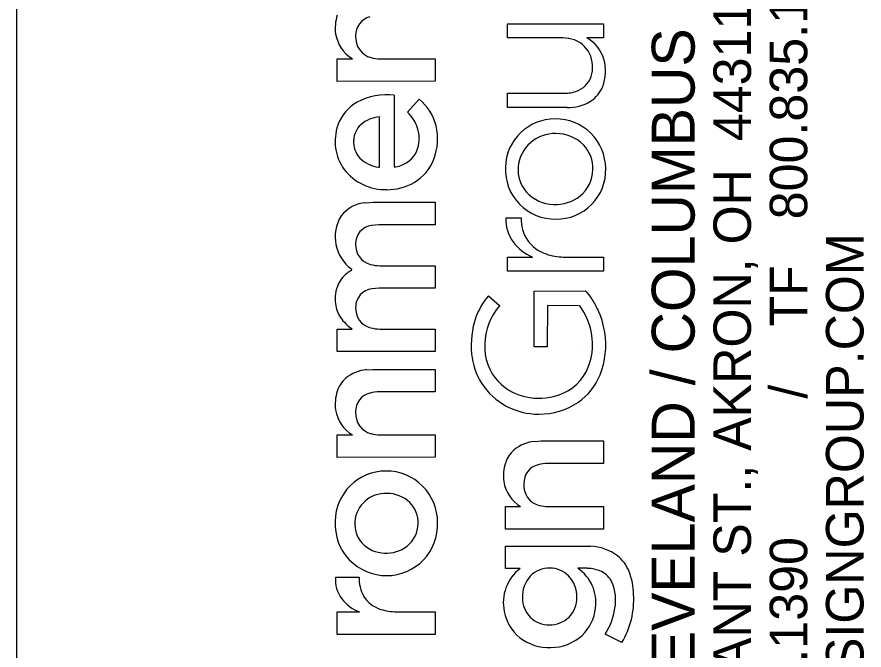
# Model space of a CAD drawing. Extents: x -0.6 to 34, y 0 to 22.
# Drawn here: x 32 to 33.125, y 3.095 to 3.936 of the extents above; entities that cross this region are included whole.
import ezdxf

# ---------------------------------------------------------------- set-up
doc = ezdxf.new("R2010")
doc.units = 0
doc.layers.add('SH_Cut_Line', color=7, linetype='Continuous')
doc.layers.add('SH_Data', color=7, linetype='Continuous')

msp = doc.modelspace()

# ---------------------------------------------------------------- linework, layer by layer
at = {"layer": 'SH_Cut_Line'}
for p, q in [((32.6515, 3.908), (32.6515, 3.9267)), ((32.6515, 3.9267), (32.7791, 3.9266)), ((32.7791, 3.9266), (32.7791, 3.908)), ((32.7249, 3.908), (32.6515, 3.908)), ((32.7328, 3.9073), (32.7249, 3.908)), ((32.7791, 3.908), (32.7569, 3.908)), ((32.4254, 3.8503), (32.4254, 3.8802)), ((32.4254, 3.8802), (32.4455, 3.8802)), ((32.4822, 3.8802), (32.5557, 3.8802)), ((32.5557, 3.8802), (32.5557, 3.8504)), ((32.5557, 3.8504), (32.4254, 3.8503)), ((32.5011, 3.8321), (32.5012, 3.7366)), ((32.5188, 3.8093), (32.5342, 3.8266)), ((32.6515, 3.8344), (32.7291, 3.8345)), ((32.6517, 3.8154), (32.6515, 3.8344)), ((32.7307, 3.8154), (32.6517, 3.8154)), ((32.4814, 3.7364), (32.4814, 3.803)), ((32.4802, 3.7363), (32.4814, 3.7364)), ((32.4633, 3.6891), (32.4726, 3.6897)), ((32.4726, 3.6897), (32.5556, 3.6897)), ((32.5556, 3.6897), (32.5557, 3.6598)), ((32.6493, 3.6691), (32.6698, 3.6691)), ((32.4806, 3.6598), (32.471, 3.6588)), ((32.5557, 3.6598), (32.4806, 3.6598)), ((32.6515, 3.598), (32.6515, 3.617)), ((32.6515, 3.617), (32.6848, 3.617)), ((32.726, 3.617), (32.7791, 3.617)), ((32.7791, 3.617), (32.779, 3.598)), ((32.4444, 3.5992), (32.4446, 3.6007)), ((32.4822, 3.6055), (32.5557, 3.6055)), ((32.5557, 3.6055), (32.5557, 3.5757)), ((32.779, 3.598), (32.6515, 3.598)), ((32.4809, 3.5757), (32.4714, 3.5747)), ((32.5557, 3.5757), (32.4809, 3.5757)), ((32.6868, 3.5718), (32.7552, 3.5719)), ((32.6868, 3.4978), (32.6868, 3.5718)), ((32.6264, 3.5655), (32.6411, 3.5524)), ((32.7045, 3.5524), (32.7043, 3.4978)), ((32.7474, 3.5523), (32.7045, 3.5524)), ((32.4254, 3.4915), (32.4254, 3.5214)), ((32.4254, 3.5214), (32.4451, 3.5214)), ((32.4821, 3.5214), (32.5557, 3.5214)), ((32.5557, 3.5214), (32.5557, 3.4916)), ((32.75, 3.5), (32.75, 3.5)), ((32.5557, 3.4916), (32.4254, 3.4915)), ((32.7043, 3.4978), (32.6868, 3.4978)), ((32.4644, 3.4674), (32.4729, 3.4678)), ((32.4729, 3.4678), (32.5557, 3.4678)), ((32.5557, 3.4678), (32.5557, 3.438)), ((32.5557, 3.438), (32.4814, 3.438)), ((32.4254, 3.3509), (32.4254, 3.3807)), ((32.4254, 3.3807), (32.4455, 3.3807)), ((32.4822, 3.3807), (32.5557, 3.3807)), ((32.5557, 3.3807), (32.5557, 3.351)), ((32.6878, 3.3722), (32.6963, 3.3727)), ((32.6963, 3.3727), (32.7792, 3.3727)), ((32.7792, 3.3727), (32.7792, 3.3429)), ((32.5557, 3.351), (32.4254, 3.3509)), ((32.7792, 3.3429), (32.7048, 3.3428)), ((32.6489, 3.2557), (32.6489, 3.2855)), ((32.6489, 3.2855), (32.669, 3.2855)), ((32.7057, 3.2855), (32.7791, 3.2855)), ((32.7791, 3.2855), (32.7792, 3.2558)), ((32.7792, 3.2558), (32.6489, 3.2557)), ((32.6489, 3.2034), (32.6489, 3.2332)), ((32.6489, 3.2332), (32.7524, 3.2332)), ((32.7524, 3.2332), (32.7619, 3.2329)), ((32.6684, 3.2034), (32.6489, 3.2034)), ((32.7576, 3.2036), (32.7449, 3.2036)), ((32.423, 3.1919), (32.4545, 3.1919)), ((32.4254, 3.1159), (32.4254, 3.1458)), ((32.4254, 3.1458), (32.4547, 3.1458)), ((32.5041, 3.1458), (32.5557, 3.1457)), ((32.5557, 3.1457), (32.5556, 3.1159)), ((32.5556, 3.1159), (32.4254, 3.1159)), ((32.8036, 3.1049), (32.7812, 3.116))]:
    msp.add_line(p, q, dxfattribs=at)
for points in [[(32.7328, 3.9073), (32.7249, 3.908), (32.6515, 3.908), (32.6515, 3.9267), (32.7791, 3.9266), (32.7791, 3.908), (32.7569, 3.908)], [(32.4254, 3.8503), (32.4254, 3.8802), (32.4455, 3.8802)], [(32.4822, 3.8802), (32.5557, 3.8802), (32.5557, 3.8504), (32.4254, 3.8503)], [(32.5011, 3.8321), (32.5012, 3.7366)], [(32.5188, 3.8093), (32.5342, 3.8266)], [(32.7307, 3.8154), (32.6517, 3.8154), (32.6515, 3.8344), (32.7291, 3.8345)], [(32.4802, 3.7363), (32.4814, 3.7364), (32.4814, 3.803)], [(32.4633, 3.6891), (32.4726, 3.6897), (32.5556, 3.6897), (32.5557, 3.6598), (32.4806, 3.6598), (32.471, 3.6588)], [(32.6493, 3.6691), (32.6698, 3.6691)], [(32.6515, 3.598), (32.6515, 3.617), (32.6848, 3.617)], [(32.726, 3.617), (32.7791, 3.617), (32.779, 3.598), (32.6515, 3.598)], [(32.4444, 3.5992), (32.4446, 3.6007)], [(32.4822, 3.6055), (32.5557, 3.6055), (32.5557, 3.5757), (32.4809, 3.5757), (32.4714, 3.5747)], [(32.7474, 3.5523), (32.7045, 3.5524), (32.7043, 3.4978), (32.6868, 3.4978), (32.6868, 3.5718), (32.7552, 3.5719)], [(32.6264, 3.5655), (32.6411, 3.5524)], [(32.4254, 3.4915), (32.4254, 3.5214), (32.4451, 3.5214)], [(32.4821, 3.5214), (32.5557, 3.5214), (32.5557, 3.4916), (32.4254, 3.4915)], [(32.4644, 3.4674), (32.4729, 3.4678), (32.5557, 3.4678), (32.5557, 3.438), (32.4814, 3.438)], [(32.4254, 3.3509), (32.4254, 3.3807), (32.4455, 3.3807)], [(32.4822, 3.3807), (32.5557, 3.3807), (32.5557, 3.351), (32.4254, 3.3509)], [(32.6878, 3.3722), (32.6963, 3.3727), (32.7792, 3.3727), (32.7792, 3.3429), (32.7048, 3.3428)], [(32.6489, 3.2557), (32.6489, 3.2855), (32.669, 3.2855)], [(32.7057, 3.2855), (32.7791, 3.2855), (32.7792, 3.2558), (32.6489, 3.2557)], [(32.6684, 3.2034), (32.6489, 3.2034), (32.6489, 3.2332), (32.7524, 3.2332), (32.7619, 3.2329)], [(32.7576, 3.2036), (32.7449, 3.2036)], [(32.423, 3.1919), (32.4545, 3.1919)], [(32.4254, 3.1159), (32.4254, 3.1458), (32.4547, 3.1458)], [(32.5041, 3.1458), (32.5557, 3.1457), (32.5556, 3.1159), (32.4254, 3.1159)], [(32.8036, 3.1049), (32.7812, 3.116)]]:
    msp.add_lwpolyline(points, dxfattribs=at)
for centre, radius, start, end in [((32.4787, 3.9211), 0.056, 162.274, 187.7917), ((32.4787, 3.9211), 0.056, 162.274, 187.7917), ((32.4748, 3.9116), 0.025, 103.6868, 182.214), ((32.4748, 3.9116), 0.025, 103.6868, 182.214), ((32.4703, 3.9209), 0.0476, 188.9646, 238.6987), ((32.4703, 3.9209), 0.0476, 188.9646, 238.6987), ((32.4774, 3.9085), 0.0276, 175.5844, 255.1382), ((32.4774, 3.9085), 0.0276, 175.5844, 255.1382), ((32.7271, 3.87), 0.0377, 33.5008, 81.3295), ((32.7271, 3.87), 0.0377, 33.5008, 81.3295), ((32.7324, 3.8648), 0.0496, 17.6221, 60.3897), ((32.7324, 3.8648), 0.0496, 17.6221, 60.3897), ((32.4818, 3.9224), 0.0421, 254.0891, 270.5284), ((32.4818, 3.9224), 0.0421, 254.0891, 270.5284), ((32.7241, 3.8695), 0.0405, 346.5618, 31.7539), ((32.7241, 3.8695), 0.0405, 346.5618, 31.7539), ((32.7234, 3.8641), 0.0584, 339.162, 15.6148), ((32.7234, 3.8641), 0.0584, 339.162, 15.6148), ((32.7337, 3.8662), 0.0304, 294.6321, 348.4863), ((32.7337, 3.8662), 0.0304, 294.6321, 348.4863), ((32.7275, 3.8808), 0.0463, 271.952, 294.0894), ((32.7275, 3.8808), 0.0463, 271.952, 294.0894), ((32.739, 3.859), 0.042, 303.1039, 338.1561), ((32.739, 3.859), 0.042, 303.1039, 338.1561), ((32.4918, 3.7487), 0.0839, 83.6212, 118.2845), ((32.4918, 3.7487), 0.0839, 83.6212, 118.2845), ((32.494, 3.7763), 0.0644, 13.5328, 51.3627), ((32.494, 3.7763), 0.0644, 13.5328, 51.3627), ((32.4789, 3.7737), 0.0558, 118.8294, 160.6224), ((32.4789, 3.7737), 0.0558, 118.8294, 160.6224), ((32.7321, 3.8726), 0.0571, 268.627, 301.4778), ((32.7321, 3.8726), 0.0571, 268.627, 301.4778), ((32.4844, 3.7607), 0.0424, 94.0131, 130.8806), ((32.4844, 3.7607), 0.0424, 94.0131, 130.8806), ((32.4803, 3.7702), 0.0549, 19.0387, 45.4432), ((32.4803, 3.7702), 0.0549, 19.0387, 45.4432), ((32.487, 3.7707), 0.0644, 160.5214, 215.7815), ((32.487, 3.7707), 0.0644, 160.5214, 215.7815), ((32.477, 3.7709), 0.0298, 132.9855, 177.1802), ((32.477, 3.7709), 0.0298, 132.9855, 177.1802), ((32.7143, 3.7348), 0.0655, 89.4821, 178.7775), ((32.7143, 3.7348), 0.0655, 89.4821, 178.7775), ((32.7158, 3.7341), 0.0662, 0.4227, 90.7613), ((32.7158, 3.7341), 0.0662, 0.4227, 90.7613), ((32.4872, 3.7743), 0.047, 344.6072, 17.0067), ((32.4872, 3.7743), 0.047, 344.6072, 17.0067), ((32.4829, 3.7738), 0.0758, 339.3543, 13.3771), ((32.4829, 3.7738), 0.0758, 339.3543, 13.3771), ((32.714, 3.7324), 0.0485, 87.6883, 175.017), ((32.714, 3.7324), 0.0485, 87.6883, 175.017), ((32.7166, 3.7304), 0.0505, 44.912, 90.7591), ((32.7166, 3.7304), 0.0505, 44.912, 90.7591), ((32.4782, 3.7697), 0.0311, 175.0014, 223.2876), ((32.4782, 3.7697), 0.0311, 175.0014, 223.2876), ((32.499, 3.7718), 0.035, 288.0108, 343.5536), ((32.499, 3.7718), 0.035, 288.0108, 343.5536), ((32.7196, 3.7345), 0.0455, 358.3228, 43.8349), ((32.7196, 3.7345), 0.0455, 358.3228, 43.8349), ((32.4855, 3.7783), 0.0423, 225.0645, 262.797), ((32.4855, 3.7783), 0.0423, 225.0645, 262.797), ((32.4955, 3.7698), 0.0626, 300.9439, 338.7322), ((32.4955, 3.7698), 0.0626, 300.9439, 338.7322), ((32.5013, 3.7568), 0.0202, 269.7004, 294.8729), ((32.5013, 3.7568), 0.0202, 269.7004, 294.8729), ((32.7148, 3.7334), 0.0661, 177.5373, 270.9452), ((32.7148, 3.7334), 0.0661, 177.5373, 270.9452), ((32.7108, 3.7331), 0.0453, 175.5147, 221.4205), ((32.7108, 3.7331), 0.0453, 175.5147, 221.4205), ((32.4891, 3.7752), 0.0687, 217.7434, 271.6561), ((32.4891, 3.7752), 0.0687, 217.7434, 271.6561), ((32.7167, 3.7327), 0.0654, 269.3083, 1.6791), ((32.7167, 3.7327), 0.0654, 269.3083, 1.6791), ((32.7193, 3.7337), 0.0457, 308.9038, 359.3095), ((32.7193, 3.7337), 0.0457, 308.9038, 359.3095), ((32.492, 3.777), 0.0706, 269.2053, 300.3357), ((32.492, 3.777), 0.0706, 269.2053, 300.3357), ((32.714, 3.7373), 0.0505, 222.6626, 268.3733), ((32.714, 3.7373), 0.0505, 222.6626, 268.3733), ((32.7157, 3.7386), 0.0518, 266.5531, 308.6725), ((32.7157, 3.7386), 0.0518, 266.5531, 308.6725), ((32.4664, 3.644), 0.0452, 93.9112, 142.3072), ((32.4664, 3.644), 0.0452, 93.9112, 142.3072), ((32.4759, 3.6437), 0.0532, 148.2879, 233.9556), ((32.4759, 3.6437), 0.0532, 148.2879, 233.9556), ((32.6988, 3.6666), 0.0495, 177.1621, 216.2802), ((32.6988, 3.6666), 0.0495, 177.1621, 216.2802), ((32.7173, 3.6664), 0.0476, 176.7699, 252.1504), ((32.7173, 3.6664), 0.0476, 176.7699, 252.1504), ((32.4738, 3.635), 0.024, 96.7576, 181.6251), ((32.4738, 3.635), 0.024, 96.7576, 181.6251), ((32.4758, 3.6324), 0.026, 175.8157, 256.1672), ((32.4758, 3.6324), 0.026, 175.8157, 256.1672), ((32.7098, 3.6755), 0.0637, 216.9153, 246.8862), ((32.7098, 3.6755), 0.0637, 216.9153, 246.8862), ((32.7269, 3.6917), 0.0747, 251.1388, 269.3469), ((32.7269, 3.6917), 0.0747, 251.1388, 269.3469), ((32.4817, 3.6505), 0.045, 254.3463, 270.6103), ((32.4817, 3.6505), 0.045, 254.3463, 270.6103), ((32.4619, 3.5645), 0.0387, 139.5245, 154.847), ((32.4619, 3.5645), 0.0387, 139.5245, 154.847), ((32.4638, 3.5627), 0.0414, 117.9163, 139.243), ((32.4638, 3.5627), 0.0414, 117.9163, 139.243), ((32.4714, 3.5612), 0.0488, 156.0638, 187.3493), ((32.4714, 3.5612), 0.0488, 156.0638, 187.3493), ((32.4742, 3.5506), 0.0243, 96.5532, 179.949), ((32.4742, 3.5506), 0.0243, 96.5532, 179.949), ((32.725, 3.5394), 0.0444, 30.9891, 47.161), ((32.725, 3.5394), 0.0444, 30.9891, 47.161), ((32.7016, 3.5019), 0.0986, 139.7948, 159.137), ((32.7016, 3.5019), 0.0986, 139.7948, 159.137), ((32.6709, 3.5002), 0.1111, 25.3031, 33.9618), ((32.6709, 3.5002), 0.1111, 25.3031, 33.9618), ((32.4646, 3.5597), 0.0418, 186.5579, 213.3885), ((32.4646, 3.5597), 0.0418, 186.5579, 213.3885), ((32.4761, 3.5486), 0.0263, 175.722, 255.7863), ((32.4761, 3.5486), 0.0263, 175.722, 255.7863), ((32.699, 3.5008), 0.0775, 138.258, 179.7006), ((32.699, 3.5008), 0.0775, 138.258, 179.7006), ((32.6789, 3.501), 0.0856, 10.0751, 36.8319), ((32.6789, 3.501), 0.0856, 10.0751, 36.8319), ((32.6704, 3.4999), 0.1117, 8.8034, 25.3348), ((32.6704, 3.4999), 0.1117, 8.8034, 25.3348), ((32.4789, 3.5708), 0.0598, 214.7043, 235.6872), ((32.4789, 3.5708), 0.0598, 214.7043, 235.6872), ((32.7187, 3.4997), 0.1154, 161.1438, 185.6281), ((32.7187, 3.4997), 0.1154, 161.1438, 185.6281), ((32.4819, 3.5652), 0.0438, 253.6672, 270.1498), ((32.4819, 3.5652), 0.0438, 253.6672, 270.1498), ((32.6842, 3.5006), 0.0804, 333.4669, 11.0367), ((32.6842, 3.5006), 0.0804, 333.4669, 11.0367), ((32.6756, 3.4998), 0.1065, 338.2887, 9.2855), ((32.6756, 3.4998), 0.1065, 338.2887, 9.2855), ((32.6881, 3.4973), 0.0668, 176.6658, 223.6912), ((32.6881, 3.4973), 0.0668, 176.6658, 223.6912), ((32.6934, 3.497), 0.0899, 185.5077, 212.0129), ((32.6934, 3.497), 0.0899, 185.5077, 212.0129), ((32.4687, 3.4177), 0.0499, 94.9706, 130.2248), ((32.4687, 3.4177), 0.0499, 94.9706, 130.2248), ((32.4635, 3.426), 0.0402, 132.2238, 161.6823), ((32.4635, 3.426), 0.0402, 132.2238, 161.6823), ((32.6987, 3.4955), 0.0652, 282.8815, 331.8147), ((32.6987, 3.4955), 0.0652, 282.8815, 331.8147), ((32.6984, 3.4917), 0.0824, 305.0306, 337.6757), ((32.6984, 3.4917), 0.0824, 305.0306, 337.6757), ((32.6921, 3.4975), 0.0891, 212.7022, 270.714), ((32.6921, 3.4975), 0.0891, 212.7022, 270.714), ((32.6905, 3.5001), 0.0704, 224.0215, 253.88), ((32.6905, 3.5001), 0.0704, 224.0215, 253.88), ((32.4787, 3.4216), 0.056, 162.274, 187.7917), ((32.4787, 3.4216), 0.056, 162.274, 187.7917), ((32.4748, 3.4121), 0.025, 103.6868, 182.214), ((32.4748, 3.4121), 0.025, 103.6868, 182.214), ((32.4811, 3.392), 0.046, 89.6051, 105.3303), ((32.4811, 3.392), 0.046, 89.6051, 105.3303), ((32.6932, 3.5125), 0.0831, 254.4535, 283.9512), ((32.6932, 3.5125), 0.0831, 254.4535, 283.9512), ((32.6943, 3.4998), 0.0914, 269.3273, 304.1963), ((32.6943, 3.4998), 0.0914, 269.3273, 304.1963), ((32.4703, 3.4214), 0.0476, 188.9646, 238.6987), ((32.4703, 3.4214), 0.0476, 188.9646, 238.6987), ((32.4774, 3.409), 0.0276, 175.5844, 255.1382), ((32.4774, 3.409), 0.0276, 175.5844, 255.1382), ((32.4818, 3.4229), 0.0421, 254.0891, 270.5284), ((32.4818, 3.4229), 0.0421, 254.0891, 270.5284), ((32.6922, 3.3225), 0.0499, 94.9706, 130.2248), ((32.6922, 3.3225), 0.0499, 94.9706, 130.2248), ((32.6869, 3.3309), 0.0402, 132.2238, 161.6823), ((32.6869, 3.3309), 0.0402, 132.2238, 161.6823), ((32.7022, 3.3264), 0.056, 162.274, 187.7917), ((32.7022, 3.3264), 0.056, 162.274, 187.7917), ((32.7045, 3.2968), 0.046, 89.6051, 105.3303), ((32.7045, 3.2968), 0.046, 89.6051, 105.3303), ((32.4901, 3.2654), 0.0674, 89.8476, 179.6405), ((32.4901, 3.2654), 0.0674, 89.8476, 179.6405), ((32.4906, 3.2647), 0.0681, 359.5401, 90.2114), ((32.4906, 3.2647), 0.0681, 359.5401, 90.2114), ((32.6983, 3.3169), 0.025, 103.6868, 182.214), ((32.6983, 3.3169), 0.025, 103.6868, 182.214), ((32.6937, 3.3262), 0.0476, 188.9646, 238.6987), ((32.6937, 3.3262), 0.0476, 188.9646, 238.6987), ((32.7008, 3.3138), 0.0276, 175.5844, 255.1382), ((32.7008, 3.3138), 0.0276, 175.5844, 255.1382), ((32.4892, 3.2626), 0.0404, 87.0481, 175.5726), ((32.4892, 3.2626), 0.0404, 87.0481, 175.5726), ((32.492, 3.26), 0.043, 45.8426, 90.9801), ((32.492, 3.26), 0.043, 45.8426, 90.9801), ((32.4946, 3.2642), 0.0382, 357.8857, 44.159), ((32.4946, 3.2642), 0.0382, 357.8857, 44.159), ((32.7053, 3.3277), 0.0421, 254.0891, 270.5284), ((32.7053, 3.3277), 0.0421, 254.0891, 270.5284), ((32.4908, 3.2621), 0.0682, 176.8344, 270.4038), ((32.4908, 3.2621), 0.0682, 176.8344, 270.4038), ((32.4873, 3.2625), 0.0385, 175.1538, 221.1471), ((32.4873, 3.2625), 0.0385, 175.1538, 221.1471), ((32.4912, 3.2614), 0.0675, 270.0624, 2.3776), ((32.4912, 3.2614), 0.0675, 270.0624, 2.3776), ((32.4945, 3.2632), 0.0383, 308.2894, 359.4347), ((32.4945, 3.2632), 0.0383, 308.2894, 359.4347), ((32.4892, 3.2661), 0.0423, 223.0999, 268.8089), ((32.4892, 3.2661), 0.0423, 223.0999, 268.8089), ((32.491, 3.2679), 0.0442, 266.5651, 308.0608), ((32.491, 3.2679), 0.0442, 266.5651, 308.0608), ((32.7591, 3.1679), 0.065, 53.4034, 87.4906), ((32.7591, 3.1679), 0.065, 53.4034, 87.4906), ((32.7652, 3.1804), 0.0514, 21.6075, 50.5577), ((32.7652, 3.1804), 0.0514, 21.6075, 50.5577), ((32.7029, 3.1581), 0.0569, 127.3748, 192.2247), ((32.7029, 3.1581), 0.0569, 127.3748, 192.2247), ((32.7069, 3.1693), 0.0346, 88.473, 136.4256), ((32.7069, 3.1693), 0.0346, 88.473, 136.4256), ((32.7081, 3.1696), 0.0342, 44.2719, 90.4762), ((32.7081, 3.1696), 0.0342, 44.2719, 90.4762), ((32.7142, 3.1583), 0.0547, 352.1125, 55.923), ((32.7142, 3.1583), 0.0547, 352.1125, 55.923), ((32.7567, 3.1572), 0.0463, 65.0169, 88.8011), ((32.7567, 3.1572), 0.0463, 65.0169, 88.8011), ((32.7626, 3.1716), 0.0309, 26.2681, 63.803), ((32.7626, 3.1716), 0.0309, 26.2681, 63.803), ((32.7307, 3.1671), 0.0884, 1.1514, 21.3627), ((32.7307, 3.1671), 0.0884, 1.1514, 21.3627), ((32.4662, 3.1888), 0.0433, 175.8731, 216.3475), ((32.4662, 3.1888), 0.0433, 175.8731, 216.3475), ((32.5009, 3.1895), 0.0464, 176.9688, 209.6064), ((32.5009, 3.1895), 0.0464, 176.9688, 209.6064), ((32.7114, 3.166), 0.0401, 137.4674, 182.3324), ((32.7114, 3.166), 0.0401, 137.4674, 182.3324), ((32.7037, 3.166), 0.04, 358.5714, 43.5376), ((32.7037, 3.166), 0.04, 358.5714, 43.5376), ((32.7357, 3.1615), 0.0595, 349.3073, 23.4307), ((32.7357, 3.1615), 0.0595, 349.3073, 23.4307), ((32.4747, 3.1972), 0.0551, 218.0981, 248.7907), ((32.4747, 3.1972), 0.0551, 218.0981, 248.7907), ((32.4951, 3.1881), 0.0408, 211.9447, 253.2028), ((32.4951, 3.1881), 0.0408, 211.9447, 253.2028), ((32.7065, 3.1637), 0.0351, 178.8821, 271.0837), ((32.7065, 3.1637), 0.0351, 178.8821, 271.0837), ((32.7082, 3.164), 0.0355, 268.2788, 1.5502), ((32.7082, 3.164), 0.0355, 268.2788, 1.5502), ((32.7054, 3.1624), 0.1138, 329.6388, 3.26), ((32.7054, 3.1624), 0.1138, 329.6388, 3.26), ((32.7099, 3.1571), 0.0589, 313.742, 353.8554), ((32.7099, 3.1571), 0.0589, 313.742, 353.8554), ((32.7074, 3.1633), 0.0877, 327.3149, 351.5748), ((32.7074, 3.1633), 0.0877, 327.3149, 351.5748), ((32.5047, 3.2165), 0.0707, 252.4655, 269.573), ((32.5047, 3.2165), 0.0707, 252.4655, 269.573), ((32.7046, 3.157), 0.0584, 190.7518, 231.2892), ((32.7046, 3.157), 0.0584, 190.7518, 231.2892), ((32.7063, 3.1611), 0.0627, 232.4606, 272.5902), ((32.7063, 3.1611), 0.0627, 232.4606, 272.5902), ((32.7095, 3.159), 0.0605, 269.6361, 312.7088), ((32.7095, 3.159), 0.0605, 269.6361, 312.7088)]:
    msp.add_arc(centre, radius, start, end, dxfattribs=at)
at = {"layer": 'SH_Data'}
msp.add_line((32, 0.5), (32, 21.5), dxfattribs=at)

# ---------------------------------------------------------------- texts
at = {"layer": 'SH_Cut_Line'}
for s, height, p in [('800.835.1390', 0.049846, (33.0497, 3.6671)), ('450 GRANT ST., AKRON, OH  44311', 0.049846, (32.9749, 2.8374)), ('AKRON / CLEVELAND / COLUMBUS', 0.056969, (32.9001, 2.638)), ('ENVDESIGNGROUP.COM', 0.049846, (33.1244, 2.8374)), ('TF', 0.04985, (33.0497, 3.5246)), ('/  ', 0.04985, (33.0497, 3.4288)), ('330.375.1390', 0.049846, (33.0497, 2.8374))]:
    msp.add_text(s, height=height, rotation=90, dxfattribs=at).set_placement(p)

doc.saveas('drawing.dxf')
